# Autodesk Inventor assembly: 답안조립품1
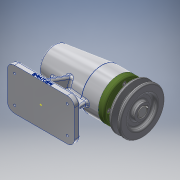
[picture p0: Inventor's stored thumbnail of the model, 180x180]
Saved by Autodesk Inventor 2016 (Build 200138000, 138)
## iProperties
Created: 2018-09
Part Number: 답안조립품1
Document SubType Name: Assembly
Designer: CAMTIC
Author: CAMTIC
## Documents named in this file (12)
- C:\Users\CAMTIC\Desktop\480907V1030\답안조립품1.iam
- C:\Users\CAMTIC\Desktop\480907V1030\본체.ipt
- C:\Users\CAMTIC\Desktop\480907V1030\베어링 6004.ipt
- C:\Users\CAMTIC\Desktop\480907V1030\베어링 51202.ipt
- C:\Users\CAMTIC\Desktop\480907V1030\볼트 M4.ipt
- C:\Users\CAMTIC\Desktop\480907V1030\어댑터슬리브.ipt
- C:\Users\CAMTIC\Desktop\480907V1030\축.ipt
- C:\Users\CAMTIC\Desktop\480907V1030\오일 실.ipt
- C:\Users\CAMTIC\Desktop\480907V1030\커버.ipt
- C:\Users\CAMTIC\Desktop\480907V1030\V벨트풀리.ipt
- C:\Users\CAMTIC\Desktop\480907V1030\멈춤나사 M3.ipt
- C:\Users\CAMTIC\Desktop\480907V1030\키 5 x 5 x 16.ipt
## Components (1 placed, 1 different names)
1. V벨트풀리:1
